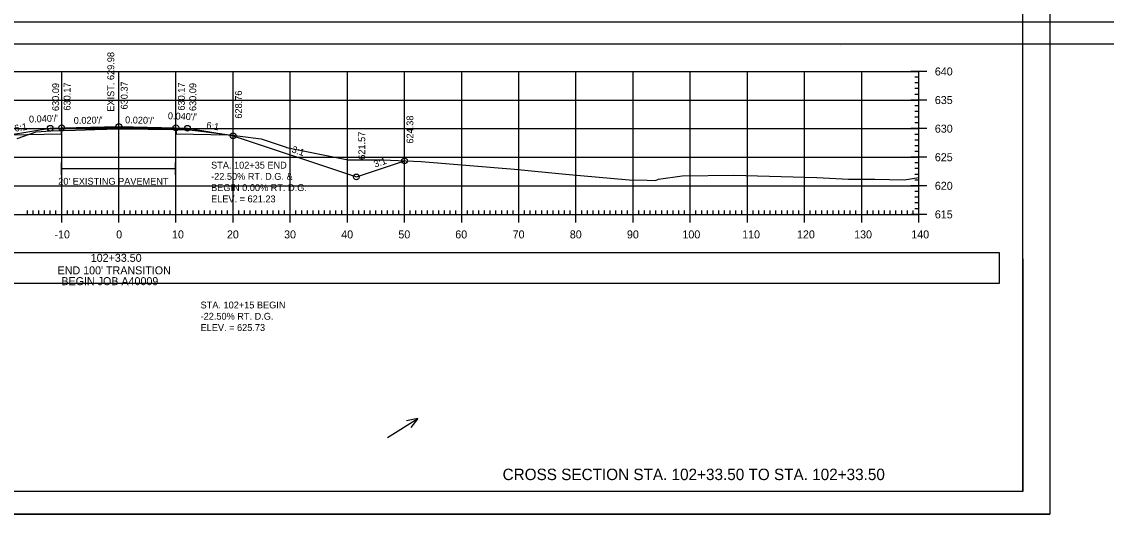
# Model space of a CAD drawing. Extents: x 1381471 to 1382703, y 370300 to 371487.
# Drawn here: x 1381987.8 to 1382177.6, y 370547.6 to 370633.8 of the extents above; entities that cross this region are included whole.
import ezdxf

# ---------------------------------------------------------------- set-up
doc = ezdxf.new("R2010")
doc.units = 0
for name, color, linetype in [('Level 15', 7, 'Continuous'), ('Level 16', 7, 'Continuous'), ('Level 18', 7, 'Continuous'), ('Level 2', 7, 'Continuous'), ('Level 20', 7, 'Continuous'), ('Level 21', 7, 'Continuous'), ('Level 22', 7, 'Continuous'), ('Level 26', 7, 'Continuous'), ('Level 4', 7, 'Continuous'), ('Level 40', 7, 'Continuous'), ('Level 41', 7, 'Continuous'), ('Level 42', 7, 'Continuous'), ('Level 45', 7, 'Continuous'), ('Level 5', 7, 'Continuous'), ('Level 6', 7, 'Continuous')]:
    doc.layers.add(name, color=color, linetype=linetype)

msp = doc.modelspace()

# ---------------------------------------------------------------- linework, layer by layer
at = {"layer": 'Level 16'}
for p, q in [((1381994.66, 370609.17), (1381994.66, 370607.03)), ((1382014.66, 370609.17), (1382014.66, 370607.03)), ((1381994.66, 370608.1), (1382014.66, 370608.1))]:
    msp.add_line(p, q, dxfattribs=at)
at = {"layer": 'Level 18'}
msp.add_lwpolyline([(1381987.01, 370613.38), (1381990.29, 370614.52), (1381990.3, 370614.53), (1381990.31, 370614.53), (1381990.31, 370614.53), (1381990.31, 370614.53), (1381990.31, 370614.53), (1381990.31, 370614.53), (1381990.33, 370614.53), (1381992.9, 370614.69), (1381997.21, 370614.82), (1382000.55, 370614.93), (1382004.86, 370615.06), (1382014.96, 370614.92), (1382017.1, 370614.9), (1382018.67, 370614.7), (1382029.69, 370613.28), (1382034.05, 370611.86), (1382034.09, 370611.85), (1382034.1, 370611.86), (1382034.12, 370611.82), (1382044.91, 370609.61), (1382050.96, 370609.65), (1382057.66, 370609.33), (1382074.02, 370608), (1382082.91, 370607.14), (1382094.07, 370606.16), (1382097.25, 370606.05), (1382098.68, 370606.04), (1382099.22, 370606.26), (1382103.36, 370606.83), (1382112.42, 370606.96), (1382126.94, 370606.55), (1382132.44, 370606.24), (1382137.04, 370606.27), (1382142.21, 370606.12), (1382144.77, 370606.55)], dxfattribs=at)
at = {"layer": 'Level 2'}
msp.add_lwpolyline([(1381985.66, 370613.99), (1381994.76, 370614.17), (1381994.77, 370615.09), (1382004.77, 370615.29), (1382014.77, 370615.08), (1382014.78, 370614.17), (1382023.91, 370613.99)], dxfattribs=at)
at = {"layer": 'Level 20'}
msp.add_lwpolyline([(1381975.49, 370610.75), (1381984.77, 370613.84), (1381985.66, 370613.99), (1381992.77, 370615.17), (1381994.77, 370615.25), (1382004.77, 370615.45), (1382014.77, 370615.25), (1382016.77, 370615.17), (1382023.91, 370613.99), (1382024.77, 370613.84), (1382045.33, 370607.03), (1382045.84, 370606.84), (1382045.85, 370606.83), (1382045.92, 370606.81), (1382046.34, 370606.65), (1382054.77, 370609.47)], dxfattribs=at)
at = {"layer": 'Level 22'}
for p, q in [((1381864.77, 370625.09), (1382144.77, 370625.09)), ((1381994.77, 370600.09), (1381994.77, 370625.09)), ((1382004.77, 370600.09), (1382004.77, 370625.09)), ((1382014.77, 370600.09), (1382014.77, 370625.09)), ((1382024.77, 370600.09), (1382024.77, 370625.09)), ((1382034.77, 370600.09), (1382034.77, 370625.09)), ((1382044.77, 370600.09), (1382044.77, 370625.09)), ((1382054.77, 370600.09), (1382054.77, 370625.09)), ((1382064.77, 370600.09), (1382064.77, 370625.09)), ((1382074.77, 370600.09), (1382074.77, 370625.09)), ((1382084.77, 370600.09), (1382084.77, 370625.09)), ((1382094.77, 370600.09), (1382094.77, 370625.09)), ((1382104.77, 370600.09), (1382104.77, 370625.09)), ((1382114.77, 370600.09), (1382114.77, 370625.09)), ((1382124.77, 370600.09), (1382124.77, 370625.09)), ((1382134.77, 370600.09), (1382134.77, 370625.09)), ((1382144.77, 370600.09), (1382144.77, 370625.09)), ((1381864.77, 370620.09), (1382144.77, 370620.09)), ((1381864.77, 370615.09), (1382144.77, 370615.09)), ((1381864.77, 370610.09), (1382144.77, 370610.09)), ((1381864.77, 370605.09), (1382144.77, 370605.09)), ((1381864.77, 370600.09), (1382144.77, 370600.09))]:
    msp.add_line(p, q, dxfattribs=at)
at = {"layer": 'Level 26'}
msp.add_line((1381834.37, 370547.63), (1382167.7, 370547.63), dxfattribs=at)
for points in [[(1381834.36, 370760.97), (1382167.7, 370760.97), (1382167.7, 370547.63), (1381834.36, 370547.63)], [(1382080.69, 370757.07), (1382100.31, 370757.07), (1382100.31, 370747.19), (1382116.42, 370747.19), (1382139.62, 370747.19), (1382139.62, 370714.52), (1382162.83, 370714.52), (1382162.95, 370551.61), (1381846.77, 370551.61), (1381846.77, 370757.07)]]:
    msp.add_lwpolyline(points, close=True, dxfattribs=at)
for centre in [(1381992.77, 370615.17), (1381994.77, 370615.25), (1382004.77, 370615.45), (1382014.77, 370615.25), (1382016.77, 370615.17), (1382024.77, 370613.84), (1382054.77, 370609.47), (1382046.34, 370606.65), (1382046.34, 370606.65)]:
    msp.add_circle(centre, 0.5, dxfattribs=at)
at = {"layer": 'Level 4'}
for p, q in [((1382146.17, 370625.09), (1382143.37, 370625.09)), ((1382144.77, 370624.09), (1382144.07, 370624.09)), ((1382144.77, 370600.09), (1382144.77, 370625.09)), ((1382144.77, 370623.09), (1382144.07, 370623.09)), ((1382144.77, 370622.09), (1382144.07, 370622.09)), ((1382146.17, 370620.09), (1382143.37, 370620.09)), ((1382144.77, 370621.09), (1382144.07, 370621.09)), ((1382144.77, 370619.09), (1382144.07, 370619.09)), ((1382144.77, 370618.09), (1382144.07, 370618.09)), ((1382144.77, 370617.09), (1382144.07, 370617.09)), ((1382146.17, 370615.09), (1382143.37, 370615.09)), ((1382144.77, 370616.09), (1382144.07, 370616.09)), ((1382144.77, 370614.09), (1382144.07, 370614.09)), ((1382144.77, 370613.09), (1382144.07, 370613.09)), ((1382144.77, 370612.09), (1382144.07, 370612.09)), ((1382144.77, 370611.09), (1382144.07, 370611.09)), ((1382146.17, 370610.09), (1382143.37, 370610.09)), ((1382144.77, 370609.09), (1382144.07, 370609.09)), ((1382144.77, 370608.09), (1382144.07, 370608.09)), ((1382144.77, 370607.09), (1382144.07, 370607.09)), ((1382146.17, 370605.09), (1382143.37, 370605.09)), ((1382144.77, 370606.09), (1382144.07, 370606.09)), ((1382144.77, 370604.09), (1382144.07, 370604.09)), ((1382144.77, 370603.09), (1382144.07, 370603.09)), ((1381994.77, 370598.69), (1381994.77, 370601.49)), ((1382004.77, 370598.69), (1382004.77, 370601.49)), ((1382014.77, 370598.69), (1382014.77, 370601.49)), ((1382024.77, 370598.69), (1382024.77, 370601.49)), ((1382034.77, 370598.69), (1382034.77, 370601.49)), ((1382044.77, 370598.69), (1382044.77, 370601.49)), ((1382054.77, 370598.69), (1382054.77, 370601.49)), ((1382064.77, 370598.69), (1382064.77, 370601.49)), ((1382074.77, 370598.69), (1382074.77, 370601.49)), ((1382084.77, 370598.69), (1382084.77, 370601.49)), ((1382094.77, 370598.69), (1382094.77, 370601.49)), ((1382104.77, 370598.69), (1382104.77, 370601.49)), ((1382114.77, 370598.69), (1382114.77, 370601.49)), ((1382124.77, 370598.69), (1382124.77, 370601.49)), ((1382134.77, 370598.69), (1382134.77, 370601.49)), ((1382144.77, 370602.09), (1382144.07, 370602.09)), ((1382144.77, 370601.09), (1382144.07, 370601.09)), ((1382144.77, 370598.69), (1382144.77, 370601.49)), ((1381864.77, 370600.09), (1382144.77, 370600.09)), ((1381988.77, 370600.09), (1381988.77, 370600.79)), ((1381989.77, 370600.09), (1381989.77, 370600.79)), ((1381990.77, 370600.09), (1381990.77, 370600.79)), ((1381991.77, 370600.09), (1381991.77, 370600.79)), ((1381992.77, 370600.09), (1381992.77, 370600.79)), ((1381993.77, 370600.09), (1381993.77, 370600.79)), ((1381995.77, 370600.09), (1381995.77, 370600.79)), ((1381996.77, 370600.09), (1381996.77, 370600.79)), ((1381997.77, 370600.09), (1381997.77, 370600.79)), ((1381998.77, 370600.09), (1381998.77, 370600.79)), ((1381999.77, 370600.09), (1381999.77, 370600.79)), ((1382000.77, 370600.09), (1382000.77, 370600.79)), ((1382001.77, 370600.09), (1382001.77, 370600.79)), ((1382002.77, 370600.09), (1382002.77, 370600.79)), ((1382003.77, 370600.09), (1382003.77, 370600.79)), ((1382005.77, 370600.09), (1382005.77, 370600.79)), ((1382006.77, 370600.09), (1382006.77, 370600.79)), ((1382007.77, 370600.09), (1382007.77, 370600.79)), ((1382008.77, 370600.09), (1382008.77, 370600.79)), ((1382009.77, 370600.09), (1382009.77, 370600.79)), ((1382010.77, 370600.09), (1382010.77, 370600.79)), ((1382011.77, 370600.09), (1382011.77, 370600.79)), ((1382012.77, 370600.09), (1382012.77, 370600.79)), ((1382013.77, 370600.09), (1382013.77, 370600.79)), ((1382015.77, 370600.09), (1382015.77, 370600.79)), ((1382016.77, 370600.09), (1382016.77, 370600.79)), ((1382017.77, 370600.09), (1382017.77, 370600.79)), ((1382018.77, 370600.09), (1382018.77, 370600.79)), ((1382019.77, 370600.09), (1382019.77, 370600.79)), ((1382020.77, 370600.09), (1382020.77, 370600.79)), ((1382021.77, 370600.09), (1382021.77, 370600.79)), ((1382022.77, 370600.09), (1382022.77, 370600.79)), ((1382023.77, 370600.09), (1382023.77, 370600.79)), ((1382025.77, 370600.09), (1382025.77, 370600.79)), ((1382026.77, 370600.09), (1382026.77, 370600.79)), ((1382027.77, 370600.09), (1382027.77, 370600.79)), ((1382028.77, 370600.09), (1382028.77, 370600.79)), ((1382029.77, 370600.09), (1382029.77, 370600.79)), ((1382030.77, 370600.09), (1382030.77, 370600.79)), ((1382031.77, 370600.09), (1382031.77, 370600.79)), ((1382032.77, 370600.09), (1382032.77, 370600.79)), ((1382033.77, 370600.09), (1382033.77, 370600.79)), ((1382035.77, 370600.09), (1382035.77, 370600.79)), ((1382036.77, 370600.09), (1382036.77, 370600.79)), ((1382037.77, 370600.09), (1382037.77, 370600.79)), ((1382038.77, 370600.09), (1382038.77, 370600.79)), ((1382039.77, 370600.09), (1382039.77, 370600.79)), ((1382040.77, 370600.09), (1382040.77, 370600.79)), ((1382041.77, 370600.09), (1382041.77, 370600.79)), ((1382042.77, 370600.09), (1382042.77, 370600.79)), ((1382043.77, 370600.09), (1382043.77, 370600.79)), ((1382045.77, 370600.09), (1382045.77, 370600.79)), ((1382046.77, 370600.09), (1382046.77, 370600.79)), ((1382047.77, 370600.09), (1382047.77, 370600.79)), ((1382048.77, 370600.09), (1382048.77, 370600.79)), ((1382049.77, 370600.09), (1382049.77, 370600.79)), ((1382050.77, 370600.09), (1382050.77, 370600.79)), ((1382051.77, 370600.09), (1382051.77, 370600.79)), ((1382052.77, 370600.09), (1382052.77, 370600.79)), ((1382053.77, 370600.09), (1382053.77, 370600.79)), ((1382055.77, 370600.09), (1382055.77, 370600.79)), ((1382056.77, 370600.09), (1382056.77, 370600.79)), ((1382057.77, 370600.09), (1382057.77, 370600.79)), ((1382058.77, 370600.09), (1382058.77, 370600.79)), ((1382059.77, 370600.09), (1382059.77, 370600.79)), ((1382060.77, 370600.09), (1382060.77, 370600.79)), ((1382061.77, 370600.09), (1382061.77, 370600.79)), ((1382062.77, 370600.09), (1382062.77, 370600.79)), ((1382063.77, 370600.09), (1382063.77, 370600.79)), ((1382065.77, 370600.09), (1382065.77, 370600.79)), ((1382066.77, 370600.09), (1382066.77, 370600.79)), ((1382067.77, 370600.09), (1382067.77, 370600.79)), ((1382068.77, 370600.09), (1382068.77, 370600.79)), ((1382069.77, 370600.09), (1382069.77, 370600.79)), ((1382070.77, 370600.09), (1382070.77, 370600.79)), ((1382071.77, 370600.09), (1382071.77, 370600.79)), ((1382072.77, 370600.09), (1382072.77, 370600.79)), ((1382073.77, 370600.09), (1382073.77, 370600.79)), ((1382075.77, 370600.09), (1382075.77, 370600.79)), ((1382076.77, 370600.09), (1382076.77, 370600.79)), ((1382077.77, 370600.09), (1382077.77, 370600.79)), ((1382078.77, 370600.09), (1382078.77, 370600.79)), ((1382079.77, 370600.09), (1382079.77, 370600.79)), ((1382080.77, 370600.09), (1382080.77, 370600.79)), ((1382081.77, 370600.09), (1382081.77, 370600.79)), ((1382082.77, 370600.09), (1382082.77, 370600.79)), ((1382083.77, 370600.09), (1382083.77, 370600.79)), ((1382085.77, 370600.09), (1382085.77, 370600.79)), ((1382086.77, 370600.09), (1382086.77, 370600.79)), ((1382087.77, 370600.09), (1382087.77, 370600.79)), ((1382088.77, 370600.09), (1382088.77, 370600.79)), ((1382089.77, 370600.09), (1382089.77, 370600.79)), ((1382090.77, 370600.09), (1382090.77, 370600.79)), ((1382091.77, 370600.09), (1382091.77, 370600.79)), ((1382092.77, 370600.09), (1382092.77, 370600.79)), ((1382093.77, 370600.09), (1382093.77, 370600.79)), ((1382095.77, 370600.09), (1382095.77, 370600.79)), ((1382096.77, 370600.09), (1382096.77, 370600.79)), ((1382097.77, 370600.09), (1382097.77, 370600.79)), ((1382098.77, 370600.09), (1382098.77, 370600.79)), ((1382099.77, 370600.09), (1382099.77, 370600.79)), ((1382100.77, 370600.09), (1382100.77, 370600.79)), ((1382101.77, 370600.09), (1382101.77, 370600.79)), ((1382102.77, 370600.09), (1382102.77, 370600.79)), ((1382103.77, 370600.09), (1382103.77, 370600.79)), ((1382105.77, 370600.09), (1382105.77, 370600.79)), ((1382106.77, 370600.09), (1382106.77, 370600.79)), ((1382107.77, 370600.09), (1382107.77, 370600.79)), ((1382108.77, 370600.09), (1382108.77, 370600.79)), ((1382109.77, 370600.09), (1382109.77, 370600.79)), ((1382110.77, 370600.09), (1382110.77, 370600.79)), ((1382111.77, 370600.09), (1382111.77, 370600.79)), ((1382112.77, 370600.09), (1382112.77, 370600.79)), ((1382113.77, 370600.09), (1382113.77, 370600.79)), ((1382115.77, 370600.09), (1382115.77, 370600.79)), ((1382116.77, 370600.09), (1382116.77, 370600.79)), ((1382117.77, 370600.09), (1382117.77, 370600.79)), ((1382118.77, 370600.09), (1382118.77, 370600.79)), ((1382119.77, 370600.09), (1382119.77, 370600.79)), ((1382120.77, 370600.09), (1382120.77, 370600.79)), ((1382121.77, 370600.09), (1382121.77, 370600.79)), ((1382122.77, 370600.09), (1382122.77, 370600.79)), ((1382123.77, 370600.09), (1382123.77, 370600.79)), ((1382125.77, 370600.09), (1382125.77, 370600.79)), ((1382126.77, 370600.09), (1382126.77, 370600.79)), ((1382127.77, 370600.09), (1382127.77, 370600.79)), ((1382128.77, 370600.09), (1382128.77, 370600.79)), ((1382129.77, 370600.09), (1382129.77, 370600.79)), ((1382130.77, 370600.09), (1382130.77, 370600.79)), ((1382131.77, 370600.09), (1382131.77, 370600.79)), ((1382132.77, 370600.09), (1382132.77, 370600.79)), ((1382133.77, 370600.09), (1382133.77, 370600.79)), ((1382135.77, 370600.09), (1382135.77, 370600.79)), ((1382136.77, 370600.09), (1382136.77, 370600.79)), ((1382137.77, 370600.09), (1382137.77, 370600.79)), ((1382138.77, 370600.09), (1382138.77, 370600.79)), ((1382139.77, 370600.09), (1382139.77, 370600.79)), ((1382140.77, 370600.09), (1382140.77, 370600.79)), ((1382141.77, 370600.09), (1382141.77, 370600.79)), ((1382142.77, 370600.09), (1382142.77, 370600.79)), ((1382146.17, 370600.09), (1382143.37, 370600.09)), ((1382143.77, 370600.09), (1382143.77, 370600.79))]:
    msp.add_line(p, q, dxfattribs=at)
at = {"layer": 'Level 40'}
for p, q in [((1382051.77, 370561.09), (1382057.11, 370564.4)), ((1382057.11, 370564.4), (1382055.11, 370563.98)), ((1382057.11, 370564.4), (1382055.85, 370562.79))]:
    msp.add_line(p, q, dxfattribs=at)
at = {"layer": 'Level 45'}
for p, q in [((1381966.21, 370633.8), (1382299.55, 370633.8)), ((1381978.61, 370629.9), (1382294.79, 370629.9)), ((1382131.13, 370629.64), (1382131.13, 370629.64)), ((1382131.13, 370629.64), (1382131.13, 370629.64))]:
    msp.add_line(p, q, dxfattribs=at)
for points in [[(1381966.21, 370633.8), (1382299.55, 370633.8), (1382299.55, 370420.46), (1381966.21, 370420.46)], [(1382212.53, 370629.9), (1382232.15, 370629.9), (1382232.15, 370620.02), (1382248.27, 370620.02), (1382271.46, 370620.02), (1382271.46, 370595.69), (1382294.79, 370595.69), (1382294.79, 370424.44), (1381978.61, 370424.44), (1381978.61, 370629.9)]]:
    msp.add_lwpolyline(points, close=True, dxfattribs=at)
at = {"layer": 'Level 6'}
for q in [(1382162.95, 370757.07), (1381846.77, 370551.61)]:
    msp.add_line((1382162.95, 370551.61), q, dxfattribs=at)
msp.add_lwpolyline([(1381850.16, 370588.04), (1382158.88, 370588.04), (1382158.88, 370593.36), (1381850.16, 370593.36)], close=True, dxfattribs=at)

# ---------------------------------------------------------------- texts
at = {"layer": 'Level 15'}
msp.add_text('CROSS SECTION STA. 102+33.50 TO STA. 102+33.50', height=2, dxfattribs=at).set_placement((1382071.93, 370553.61))
at = {"layer": 'Level 21'}
msp.add_text("20' EXISTING PAVEMENT", height=1.2, dxfattribs=at).set_placement((1381994.17, 370605.28))
at = {"layer": 'Level 41'}
for s, p in [('EXIST. 629.98', (1382003.97, 370618.06)), ('630.09', (1381994.32, 370618.17)), ('630.17', (1381996.32, 370618.25)), ('630.37', (1382006.32, 370618.45)), ('630.17', (1382016.32, 370618.25)), ('630.09', (1382018.32, 370618.17)), ('628.76', (1382026.32, 370616.84)), ('624.38', (1382056.32, 370612.47)), ('621.57', (1382047.89, 370609.65))]:
    msp.add_text(s, height=1.2, rotation=90, dxfattribs=at).set_placement(p)
at = {"layer": 'Level 42'}
for s, rotation, p in [("0.040'/'", 2.2906, (1381989.07, 370616.14)), ("0.020'/'", 1.1458, (1381996.89, 370615.91)), ("0.020'/'", 358.8542, (1382005.86, 370616.03)), ("0.040'/'", 357.7094, (1382013.34, 370616.75)), ('6:1', 350.5377, (1382020.01, 370615.14)), ('6:1', 9.4623, (1381986.6, 370614.53)), ('3:1', 341.5651, (1382034.92, 370610.98)), ('3:1', 18.4349, (1382049.61, 370608.27))]:
    msp.add_text(s, height=1.2, rotation=rotation, dxfattribs=at).set_placement(p)
at = {"layer": 'Level 5'}
for s, height, p in [('640', 1.4, (1382147.57, 370624.39)), ('635', 1.4, (1382147.57, 370619.39)), ('630', 1.4, (1382147.57, 370614.39)), ('625', 1.4, (1382147.57, 370609.39)), ('STA. 102+35 END', 1.2, (1382020.92, 370608.1)), ('-22.50% RT. D.G. &', 1.2, (1382020.92, 370606.14)), ('BEGIN 0.00% RT. D.G.', 1.2, (1382020.92, 370604.17)), ('620', 1.4, (1382147.57, 370604.39)), ('ELEV. = 621.23', 1.2, (1382020.92, 370602.2)), ('615', 1.4, (1382147.57, 370599.39)), ('-10', 1.4, (1381993.51, 370595.89)), ('0', 1.4, (1382004.31, 370595.89)), ('10', 1.4, (1382014.08, 370595.89)), ('20', 1.4, (1382023.69, 370595.89)), ('30', 1.4, (1382033.69, 370595.89)), ('40', 1.4, (1382043.69, 370595.89)), ('50', 1.4, (1382053.69, 370595.89)), ('60', 1.4, (1382063.65, 370595.89)), ('70', 1.4, (1382073.69, 370595.89)), ('80', 1.4, (1382083.69, 370595.89)), ('90', 1.4, (1382093.69, 370595.89)), ('100', 1.4, (1382103.4, 370595.89)), ('110', 1.4, (1382113.85, 370595.89)), ('120', 1.4, (1382123.45, 370595.89)), ('130', 1.4, (1382133.45, 370595.89)), ('140', 1.4, (1382143.45, 370595.89)), ('102+33.50', 1.4, (1381999.86, 370591.79)), ("END 100' TRANSITION", 1.4, (1381994.06, 370589.6)), ('BEGIN JOB A40009', 1.4, (1381994.72, 370587.71)), ('STA. 102+15 BEGIN', 1.2, (1382019.08, 370583.64)), ('-22.50% RT. D.G. ', 1.2, (1382019.08, 370581.67)), ('ELEV. = 625.73', 1.2, (1382019.08, 370579.7))]:
    msp.add_text(s, height=height, dxfattribs=at).set_placement(p)

doc.saveas('drawing.dxf')
